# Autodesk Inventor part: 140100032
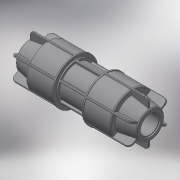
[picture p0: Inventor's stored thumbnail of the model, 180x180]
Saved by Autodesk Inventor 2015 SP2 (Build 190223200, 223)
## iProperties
Created: 2018-02
Part Number: 140100032
Material: Generic
Description: PLASSON L.14 COUPLER (SILVER) 32
Document SubType Name: Modeling
Designer: KIM
Mass: 166.028 g
Surface Area: 396.425 cm^2
Volume: 166.028 cm^3
Density: 1 g/cm^3
Appearance: Default
Author: KIM
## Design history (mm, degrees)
derived "140100.ipt"
feature "Solid1::140100.ipt"
tag "TaggingFeature1"
body "Solid1"
other parameters: "d30" = 1, "d36" = 1.14, "d65" = 59.17, "d77" = 29.44, "d93" = 44.8, "d95" = 17.1, "d96" = 1.14, "d97" = 35.2, "d100" = 45.75, "d102" = 43.32, "d103" = 1.14, "d107" = 62.65, "d113" = 61, "d114" = 3.2, "d115" = 1.6, "d117" = 0, "d126" = 6.1, "d127" = 0.61, "d129" = 360 deg, "d131" = 1.14, "d132" = 61, "d138" = 100 deg, "d139" = 51.85, "d141" = 114, "d142" = 32, "d143" = 56, "d144" = 0, "d145" = 32, "d146" = 56, "d147" = 0, "d149" = 3.05, "d150" = 1.525, "d152" = 0, "d153" = 0.61, "d155" = 360 deg, "E_" = 61, "l_" = 56, "d_" = 32, "H_" = 114
